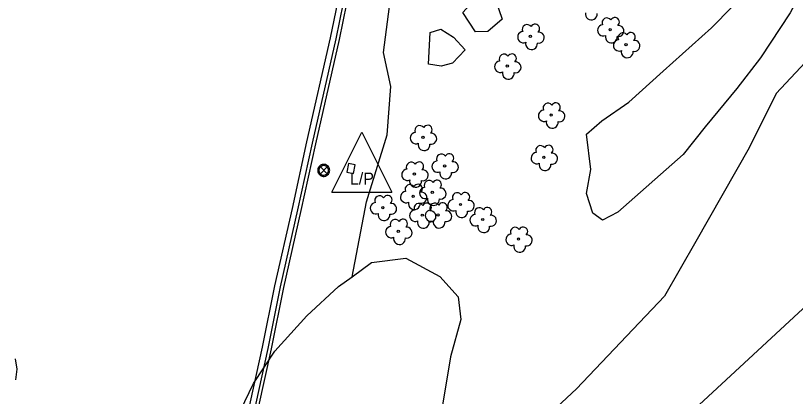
# Model space of a CAD drawing. Extents: x 2161152 to 2175754, y 602179 to 617749.
# Drawn here: x 2163408.1 to 2163537.9, y 606016.5 to 606080 of the extents above; entities that cross this region are included whole.
import ezdxf

# ---------------------------------------------------------------- set-up
doc = ezdxf.new("R2010")
doc.units = 0
for name, color, linetype in [('RD_EX_BldgApp_Post', 7, 'Continuous'), ('RD_EX_Conc_Curb', 7, 'Continuous'), ('RD_EX_Conc_Gutter', 7, 'Continuous'), ('RD_EX_Road', 7, 'Continuous'), ('RD_EX_UT', 7, 'Continuous'), ('RD_EX_VEG', 7, 'Continuous')]:
    doc.layers.add(name, color=color, linetype=linetype)

msp = doc.modelspace()

# ---------------------------------------------------------------- linework, layer by layer
at = {"layer": 'RD_EX_BldgApp_Post'}
for p, q in [((2163459.95, 606053.63), (2163458.82, 606054.77)), ((2163458.82, 606053.63), (2163459.95, 606054.77))]:
    msp.add_line(p, q, dxfattribs=at)
for points in [[(2163460.39, 606054.2), (2163460.37, 606054.35), (2163460.33, 606054.52), (2163460.26, 606054.68), (2163460.16, 606054.84), (2163460.02, 606054.97), (2163459.86, 606055.08), (2163459.67, 606055.16), (2163459.48, 606055.2), (2163459.3, 606055.2), (2163459.13, 606055.17), (2163458.97, 606055.11), (2163458.84, 606055.04), (2163458.71, 606054.94), (2163458.6, 606054.82), (2163458.5, 606054.67), (2163458.42, 606054.49), (2163458.39, 606054.3), (2163458.39, 606054.1), (2163458.42, 606053.91), (2163458.5, 606053.73), (2163458.6, 606053.58), (2163458.71, 606053.45), (2163458.84, 606053.36), (2163458.97, 606053.29), (2163459.13, 606053.23), (2163459.3, 606053.2), (2163459.48, 606053.2), (2163459.67, 606053.24), (2163459.86, 606053.32), (2163460.02, 606053.43), (2163460.16, 606053.56), (2163460.26, 606053.72), (2163460.33, 606053.88), (2163460.37, 606054.05), (2163460.39, 606054.2)], [(2163460.18, 606054.2), (2163460.18, 606054.32), (2163460.14, 606054.45), (2163460.09, 606054.58), (2163460, 606054.71), (2163459.89, 606054.82), (2163459.76, 606054.91), (2163459.62, 606054.97), (2163459.46, 606055), (2163459.32, 606055), (2163459.18, 606054.97), (2163459.05, 606054.93), (2163458.95, 606054.87), (2163458.85, 606054.8), (2163458.75, 606054.7), (2163458.67, 606054.57), (2163458.62, 606054.43), (2163458.58, 606054.28), (2163458.58, 606054.12), (2163458.62, 606053.97), (2163458.67, 606053.83), (2163458.75, 606053.7), (2163458.85, 606053.6), (2163458.95, 606053.53), (2163459.05, 606053.47), (2163459.18, 606053.42), (2163459.32, 606053.4), (2163459.46, 606053.4), (2163459.62, 606053.43), (2163459.76, 606053.49), (2163459.89, 606053.58), (2163460, 606053.69), (2163460.09, 606053.81), (2163460.14, 606053.95), (2163460.18, 606054.08), (2163460.18, 606054.2)]]:
    msp.add_lwpolyline(points, dxfattribs=at)
at = {"layer": 'RD_EX_Conc_Curb'}
for points in [[(2163443.72, 605995.42), (2163450.13, 606024.55), (2163452.19, 606034.78), (2163455.07, 606047.63), (2163457.51, 606058.72), (2163461.44, 606076.09), (2163464.52, 606091.14)], [(2163465.01, 606091.04), (2163461.93, 606075.98), (2163458, 606058.61), (2163455.56, 606047.52), (2163452.68, 606034.68), (2163450.62, 606024.45), (2163444.2, 605995.31)]]:
    msp.add_lwpolyline(points, dxfattribs=at)
at = {"layer": 'RD_EX_Conc_Gutter'}
for points in [[(2163463.54, 606091.35), (2163460.46, 606076.3), (2163456.53, 606058.94), (2163454.1, 606047.84), (2163451.21, 606034.99), (2163449.15, 606024.76), (2163442.74, 605995.64)], [(2163408, 606022.82), (2163408.26, 606021.06), (2163408.05, 606019.29)]]:
    msp.add_lwpolyline(points, dxfattribs=at)
at = {"layer": 'RD_EX_Road'}
msp.add_lwpolyline([(2163543.67, 606035.28), (2163521.89, 606015.12), (2163497.87, 605993.1), (2163491.79, 605987.49), (2163474.26, 605971.23), (2163458.77, 605956.92), (2163458.63, 605956.79), (2163440.67, 605940.14), (2163419.95, 605920.88)], dxfattribs=at)
at = {"layer": 'RD_EX_UT'}
for p, q in [((2163460.75, 606050.56), (2163465.75, 606060.56)), ((2163465.75, 606060.56), (2163470.75, 606050.56)), ((2163460.75, 606050.56), (2163470.75, 606050.56))]:
    msp.add_line(p, q, dxfattribs=at)
msp.add_lwpolyline([(2163463.24, 606053.9), (2163464.34, 606053.69), (2163464.61, 606055.15), (2163463.52, 606055.36), (2163463.24, 606053.9)], dxfattribs=at)
at = {"layer": 'RD_EX_VEG'}
for points in [[(2163464.1, 606036.47), (2163466.48, 606048.95), (2163469.97, 606060.12), (2163470.53, 606068.2), (2163469.36, 606073.82), (2163471.01, 606086.68), (2163477.33, 606115.89), (2163479.93, 606120.79), (2163483.77, 606125.42), (2163485.45, 606127.46), (2163487.67, 606130.86), (2163490.06, 606134.65), (2163492.05, 606137.09), (2163495.42, 606140.53), (2163505.05, 606150.13), (2163515.84, 606159.28), (2163520.91, 606162.37), (2163527.28, 606165.21), (2163539.36, 606168.29), (2163569.55, 606173.33), (2163587.23, 606176.36), (2163607.39, 606178.3)], [(2163541.48, 606088.78), (2163537.07, 606080.45), (2163532.11, 606072.93), (2163528.19, 606067.84), (2163522.92, 606061.45), (2163519.22, 606056.84), (2163508.34, 606047.24), (2163505.82, 606045.92), (2163504.21, 606047.07), (2163503.15, 606050.36), (2163503.84, 606054.32), (2163503.13, 606060.22), (2163505.67, 606062.43), (2163510.16, 606065.56), (2163515.9, 606070.71), (2163523.94, 606077.97), (2163530.83, 606085.02), (2163534.94, 606090.02), (2163538.07, 606094.96)], [(2163489.09, 606079.37), (2163486.69, 606077.34), (2163484.63, 606077.27), (2163482.56, 606080.5), (2163485.4, 606083.69), (2163488.06, 606082.42), (2163489.09, 606079.37)], [(2163480.8, 606072.06), (2163478.93, 606071.57), (2163476.82, 606071.91), (2163477.13, 606077.19), (2163478.89, 606077.75), (2163480.99, 606076.39), (2163482.93, 606074.29), (2163480.8, 606072.06)], [(2163540.36, 606073.06), (2163534.71, 606066.99), (2163530.21, 606057.93), (2163521.33, 606042.34), (2163516.13, 606033.27), (2163501.47, 606017.8), (2163485.93, 606003.31), (2163471.88, 605989.71), (2163463.82, 605982.19), (2163451.76, 605973.82), (2163447.68, 605972.3)], [(2163444.07, 606011.22), (2163447.68, 606018.67), (2163451.24, 606024.09), (2163456.56, 606029.96), (2163461.85, 606034.83), (2163464.1, 606036.47), (2163467.35, 606038.84), (2163473.03, 606039.58), (2163478.72, 606036.53), (2163481.79, 606033.11), (2163482.2, 606029.33), (2163480.5, 606023.12), (2163477.91, 606007.42)]]:
    msp.add_lwpolyline(points, dxfattribs=at)
for centre in [(2163507.08, 606077.63), (2163493.8, 606076.52), (2163509.73, 606075.14), (2163489.94, 606071.58), (2163497.25, 606063.42), (2163475.9, 606059.69), (2163496.03, 606056.36), (2163479.51, 606054.94), (2163474.48, 606053.59), (2163474.28, 606049.86), (2163477.46, 606050.54), (2163469.23, 606048), (2163482.16, 606048.51), (2163475.79, 606046.74), (2163478.41, 606046.78), (2163485.85, 606046.02), (2163471.8, 606044.04), (2163491.82, 606042.75)]:
    msp.add_circle(centre, 0.188, dxfattribs=at)
for centre, radius, start, end in [((2163503.94, 606080.24), 0.988, 166.8827, 5.7589), ((2163506.54, 606078.79), 0.813, 34.9763, 204.756), ((2163507.87, 606078.91), 0.746, 308.7626, 152.0467), ((2163493.25, 606077.68), 0.813, 34.9763, 204.756), ((2163494.58, 606077.8), 0.746, 308.7626, 152.0467), ((2163505.91, 606077.52), 0.943, 96.4518, 294.734), ((2163508.46, 606077.42), 0.914, 256.5667, 98.1046), ((2163492.62, 606076.4), 0.943, 96.4518, 294.734), ((2163495.18, 606076.31), 0.914, 256.5667, 98.1046), ((2163509.19, 606076.3), 0.813, 34.9763, 204.756), ((2163510.52, 606076.41), 0.746, 308.7626, 152.0467), ((2163493.98, 606075.32), 0.988, 166.8827, 5.7589), ((2163507.27, 606076.43), 0.988, 166.8827, 5.7589), ((2163508.56, 606075.02), 0.943, 96.4518, 294.734), ((2163511.11, 606074.93), 0.914, 256.5667, 98.1046), ((2163509.92, 606073.94), 0.988, 166.8827, 5.7589), ((2163489.4, 606072.74), 0.813, 34.9763, 204.756), ((2163490.72, 606072.85), 0.746, 308.7626, 152.0467), ((2163488.77, 606071.46), 0.943, 96.4518, 294.734), ((2163491.32, 606071.37), 0.914, 256.5667, 98.1046), ((2163490.12, 606070.38), 0.988, 166.8827, 5.7589), ((2163496.71, 606064.58), 0.813, 34.9763, 204.756), ((2163498.03, 606064.7), 0.746, 308.7626, 152.0467), ((2163496.07, 606063.3), 0.943, 96.4518, 294.734), ((2163498.63, 606063.21), 0.914, 256.5667, 98.1046), ((2163475.36, 606060.85), 0.813, 34.9763, 204.756), ((2163476.69, 606060.97), 0.746, 308.7626, 152.0467), ((2163497.43, 606062.22), 0.988, 166.8827, 5.7589), ((2163474.73, 606059.57), 0.943, 96.4518, 294.734), ((2163477.28, 606059.48), 0.914, 256.5667, 98.1046), ((2163476.09, 606058.49), 0.988, 166.8827, 5.7589), ((2163495.49, 606057.52), 0.813, 34.9763, 204.756), ((2163496.82, 606057.63), 0.746, 308.7626, 152.0467), ((2163478.97, 606056.11), 0.813, 34.9763, 204.756), ((2163480.29, 606056.22), 0.746, 308.7626, 152.0467), ((2163494.86, 606056.24), 0.943, 96.4518, 294.734), ((2163497.41, 606056.15), 0.914, 256.5667, 98.1046), ((2163473.94, 606054.75), 0.813, 34.9763, 204.756), ((2163475.27, 606054.86), 0.746, 308.7626, 152.0467), ((2163478.34, 606054.83), 0.943, 96.4518, 294.734), ((2163480.89, 606054.74), 0.914, 256.5667, 98.1046), ((2163496.22, 606055.16), 0.988, 166.8827, 5.7589), ((2163473.31, 606053.47), 0.943, 96.4518, 294.734), ((2163475.86, 606053.38), 0.914, 256.5667, 98.1046), ((2163479.69, 606053.75), 0.988, 166.8827, 5.7589), ((2163474.67, 606052.39), 0.988, 166.8827, 5.7589), ((2163476.92, 606051.7), 0.813, 34.9763, 204.756), ((2163478.25, 606051.82), 0.746, 308.7626, 152.0467), ((2163473.73, 606051.02), 0.813, 34.9763, 204.756), ((2163475.06, 606051.14), 0.746, 308.7626, 152.0467), ((2163476.29, 606050.42), 0.943, 96.4518, 294.734), ((2163478.84, 606050.33), 0.914, 256.5667, 98.1046), ((2163468.69, 606049.16), 0.813, 34.9763, 204.756), ((2163470.02, 606049.28), 0.746, 308.7626, 152.0467), ((2163473.1, 606049.75), 0.943, 96.4518, 294.734), ((2163475.65, 606049.65), 0.914, 256.5667, 98.1046), ((2163477.65, 606049.34), 0.988, 166.8827, 5.7589), ((2163481.62, 606049.67), 0.813, 34.9763, 204.756), ((2163482.94, 606049.78), 0.746, 308.7626, 152.0467), ((2163468.06, 606047.89), 0.943, 96.4518, 294.734), ((2163470.61, 606047.79), 0.914, 256.5667, 98.1046), ((2163474.46, 606048.67), 0.988, 166.8827, 5.7589), ((2163475.24, 606047.9), 0.813, 34.9763, 204.756), ((2163476.57, 606048.02), 0.746, 308.7626, 152.0467), ((2163477.87, 606047.94), 0.813, 34.9763, 204.756), ((2163479.2, 606048.06), 0.746, 308.7626, 152.0467), ((2163480.98, 606048.39), 0.943, 96.4518, 294.734), ((2163483.54, 606048.3), 0.914, 256.5667, 98.1046), ((2163469.42, 606046.81), 0.988, 166.8827, 5.7589), ((2163474.61, 606046.63), 0.943, 96.4518, 294.734), ((2163477.24, 606046.67), 0.943, 96.4518, 294.734), ((2163477.16, 606046.53), 0.914, 256.5667, 98.1046), ((2163479.79, 606046.57), 0.914, 256.5667, 98.1046), ((2163482.34, 606047.31), 0.988, 166.8827, 5.7589), ((2163485.31, 606047.18), 0.813, 34.9763, 204.756), ((2163486.63, 606047.29), 0.746, 308.7626, 152.0467), ((2163471.26, 606045.2), 0.813, 34.9763, 204.756), ((2163472.58, 606045.32), 0.746, 308.7626, 152.0467), ((2163475.97, 606045.55), 0.988, 166.8827, 5.7589), ((2163478.6, 606045.58), 0.988, 166.8827, 5.7589), ((2163484.68, 606045.9), 0.943, 96.4518, 294.734), ((2163487.23, 606045.81), 0.914, 256.5667, 98.1046), ((2163470.63, 606043.92), 0.943, 96.4518, 294.734), ((2163473.18, 606043.83), 0.914, 256.5667, 98.1046), ((2163486.03, 606044.82), 0.988, 166.8827, 5.7589), ((2163491.28, 606043.91), 0.813, 34.9763, 204.756), ((2163492.6, 606044.02), 0.746, 308.7626, 152.0467), ((2163471.99, 606042.84), 0.988, 166.8827, 5.7589), ((2163490.65, 606042.63), 0.943, 96.4518, 294.734), ((2163493.2, 606042.54), 0.914, 256.5667, 98.1046), ((2163492, 606041.55), 0.988, 166.8827, 5.7589)]:
    msp.add_arc(centre, radius, start, end, dxfattribs=at)

# ---------------------------------------------------------------- texts
at = {"layer": 'RD_EX_UT'}
msp.add_text('L/P', height=2, dxfattribs=at).set_placement((2163463.74, 606051.84))

doc.saveas('drawing.dxf')
